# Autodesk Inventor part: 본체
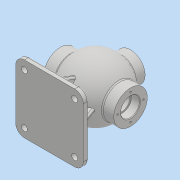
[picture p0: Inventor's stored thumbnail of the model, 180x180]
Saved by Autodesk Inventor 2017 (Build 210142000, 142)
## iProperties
Part Number: 본체
Material: 일반
Document SubType Name: Modeling
Designer: MRC
Density: 1 g/cm^3
Appearance: 기본값
Author: MRC
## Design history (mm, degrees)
sketch "스케치1"
  geometry: L1 (0, 54)-(0, -54); A1 r 54 centre (0, 0) between (0, -54) and (0, 54); 1 further point
  constraints: 2 end point, 2 point on circle, 1 centre point, 1 coincident, 1 midpoint, 1 vertical
  dimensions: "d0" = 108 diameter of A1
revolve "회전1" sketch "스케치1" stored, may be unused: angle "d1" = 90 deg
feature "쉘1" dims "d2" = 10
node "작업 평면1"
sketch "스케치2"
  geometry: C1 r 31 at (0, 0); 1 further point
  constraints: 1 centre point, 1 coincident
  dimensions: "d4" = 62 diameter of C1
extrude "돌출1" join sketch "스케치2" stored distance "d5" = 10; taper "d6" = 0 deg
sketch "스케치3"
  geometry: C1 r 31 at (0, 0) reference; C2 r 17.5 at (0, 0)
  constraints: 1 centre point, 1 coincident
  dimensions: "d7" = 35 diameter of C2
extrude "돌출2" cut sketch "스케치3" distance "d8" = 16; taper "d9" = 0 deg
sketch "스케치4"
  geometry: C1 r 17.5 at (0, 0) reference; C2 r 15 at (0, 0)
  constraints: 1 centre point, 1 coincident
  dimensions: "d10" = 30 diameter of C2
extrude "돌출3" cut sketch "스케치4" stored distance "d11" = 16; taper "d12" = 0 deg
sketch "스케치5" dims "d13" = 48
  geometry: C1 r 17.5 at (0, 0) reference; C2 r 31 at (0, 0) reference; 2 further points
  constraints: 2 vertical alignment, 1 coincident, 2 other
hole "구멍1" sketch "스케치5" at (0, 24) diameter "d14" = 3.242; stored, may be unused: countersink angle "d18" = 90 deg, drill point angle "d20" = 118 deg; dims "d15" = 12, "d16" = 4, "d17" = 2, "d19" = 15
node "작업 평면2"
sketch "스케치6"
  geometry: C1 r 27 at (0, 0); 1 further point
  constraints: 1 centre point, 1 coincident
  dimensions: "d25" = 54 diameter of C1
extrude "돌출4" join sketch "스케치6" stored distance "d26" = 16; taper "d27" = 0 deg
sketch "스케치7"
  geometry: C1 r 27 at (0, 0) reference; C2 r 13 at (0, 0)
  constraints: 1 centre point, 1 coincident
  dimensions: "d28" = 26 diameter of C2
extrude "돌출5" cut sketch "스케치7" stored distance "d29" = 16; taper "d30" = 0 deg
sketch "스케치8" dims "d31" = 40
  geometry: C1 r 13 at (0, 0) reference; C2 r 27 at (0, 0) reference; 2 further points
  constraints: 2 vertical alignment, 1 coincident, 2 other
hole "구멍2" sketch "스케치8" at (0, 20) diameter "d32" = 3.242; stored, may be unused: countersink angle "d36" = 90 deg, drill point angle "d38" = 118 deg; dims "d33" = 9, "d34" = 4, "d35" = 2, "d37" = 11
node "작업 평면3"
sketch "스케치9"
  geometry: L1 (62.5, 62.5)-(-62.5, 62.5); L2 (-62.5, 62.5)-(-62.5, -62.5); L3 (-62.5, -62.5)-(62.5, -62.5); L4 (62.5, -62.5)-(62.5, 62.5); L5 (62.5, 62.5)-(-62.5, -62.5); L6 (-62.5, 62.5)-(62.5, -62.5); 1 further point
  constraints: 12 end point, 2 midpoint, 2 parallel, 1 horizontal, 1 perpendicular
  dimensions: "d43" = 125 distance of L3.end L2.end; "d44" = 125 distance of L2.end L1.end
extrude "돌출6" join sketch "스케치9" distance "d45" = 10; taper "d46" = 0 deg
fillet "모깎기1" dims "d49" = 16
fillet "모깎기2" dims "d50" = 3
sketch "스케치11"
  geometry: L1 (-50.5, 4)-(50.5, 4); L2 (50.5, 4)-(50.5, -4); L3 (50.5, -4)-(-50.5, -4); L4 (-50.5, -4)-(-50.5, 4); L5 (-50.5, 4)-(50.5, -4); L6 (50.5, 4)-(-50.5, -4); L7 (-62.5, 46.5)-(-62.5, -46.5) reference; 1 further point
  constraints: 12 end point, 2 midpoint, 2 parallel, 1 horizontal, 1 perpendicular
  dimensions: "d51" = 8 distance of L1.end L2.end; "d52" = 12 distance between parallel lines of L4 L7
extrude "돌출7" join sketch "스케치11" stored distance "d53" = 10; taper "d54" = 0 deg
feature "면 기울기1" dims angle "d55" = 20 deg
sketch "스케치13"
  geometry: L1 (-75, -50.5)-(-50.221, -41.481); L2 (-75, -46.5)-(-75, -59.5) reference; L3 (-78, -62.5)-(-85, -62.5) reference; 1 further point
  constraints: 2 end point, 1 point on line
  dimensions: "d56" = 20 deg angle of L1 L3; "d57" = 12 distance from line of L3 L1.start
feature "리브1" sketch "스케치13" dims "d58" = 1, "d59" = 8, "d60" = 0, "d61" = 0, "d62" = 1, "d63" = 1
sketch "스케치14"
  geometry: C1 r 5.5 at (-46.5, -46.5); C2 r 5.5 at (-46.5, 46.5); C3 r 5.5 at (46.5, 46.5); C4 r 5.5 at (46.5, -46.5); A1 r 13 centre (-46.5, 46.5) between (-46.5, 59.5) and (-59.5, 46.5) reference; A2 r 13 centre (-46.5, -46.5) between (-59.5, -46.5) and (-46.5, -59.5) reference; A3 r 13 centre (46.5, 46.5) between (59.5, 46.5) and (46.5, 59.5) reference; A4 r 16 centre (46.5, -46.5) between (46.5, -62.5) and (62.5, -46.5) reference; 1 further point
  constraints: 4 centre point, 4 coincident
  dimensions: "d64" = 11 diameter of C1; "d65" = 11 diameter of C2; "d66" = 11 diameter of C3; "d67" = 11 diameter of C4
extrude "돌출8" cut sketch "스케치14" stored distance "d68" = 10; taper "d69" = 0 deg
chamfer "모따기1" distance "d70" = 1; stored, may be unused: second distance "d71" = 2, angle "d72" = 45 deg
fillet "모깎기3" dims "d73" = 3
fillet "모깎기4" dims "d74" = 3
chamfer "모따기2" distance "d75" = 1; stored, may be unused: second distance "d76" = 2, angle "d77" = 45 deg
fillet "모깎기5" dims "d78" = 3
chamfer "모따기3" distance "d79" = 1; stored, may be unused: second distance "d80" = 2, angle "d81" = 45 deg
fillet "모깎기6" dims "d82" = 3
fillet "모깎기7" dims "d83" = 3
fillet "모깎기8" dims "d84" = 0.6
fillet "모깎기9" dims "d85" = 0.6
node "작업 평면4"
sketch "스케치16"
  geometry: L1 (-27, 65)-(27, 65) reference; 2 further points
  constraints: 1 vertical alignment, 1 other
  dimensions: "d87" = 9 distance from line of point (0, 56) L1
feature "엠보싱1" sketch "스케치16" dims "d88" = 0.5, "d89" = 0
node "솔리드1"
pattern_circular "원형 패턴1" dims angle "d22" = 360 deg
mirror "미러1"
pattern_circular "원형 패턴2" dims angle "d40" = 360 deg
mirror "미러2"
other parameters: "d3" = 65, "d24" = 65, "d42" = -85, "d86" = -45.75
